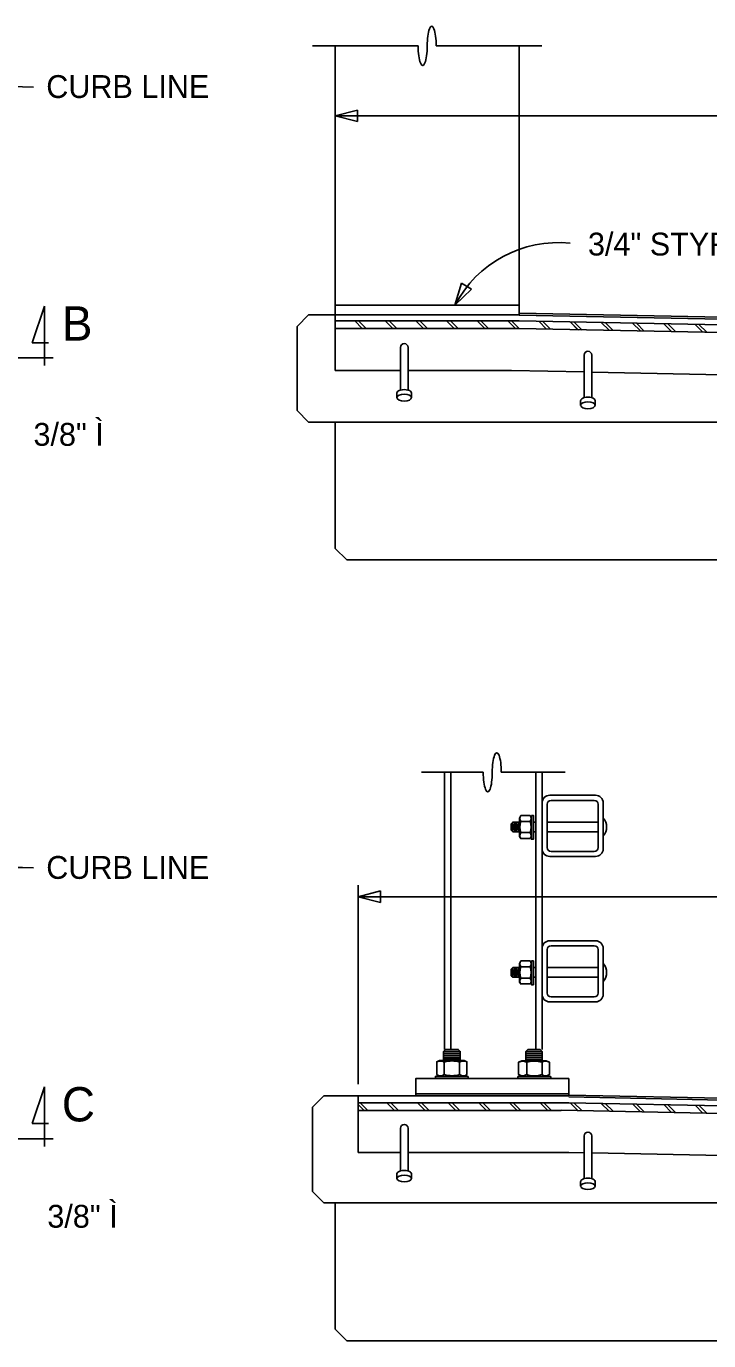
# Model space of a CAD drawing. Extents: x 19590 to 20151, y 19944 to 20103.
# Drawn here: x 19645.16 to 19659.09, y 20050.86 to 20077.69 of the extents above; entities that cross this region are included whole.
import ezdxf

# ---------------------------------------------------------------- set-up
doc = ezdxf.new("R2010")
doc.units = 0
doc.layers.add('DETAIL_PR', color=7, linetype='Continuous')
doc.layers.add('DETAIL_TEXT_DIMEN_PR', color=7, linetype='Continuous')

msp = doc.modelspace()

# ---------------------------------------------------------------- linework, layer by layer
at = {"layer": 'DETAIL_PR'}
for p, q in [((19650.997, 20077.285), (19653.156, 20077.285)), ((19651.466, 20071.795), (19651.466, 20077.285)), ((19653.525, 20077.285), (19655.684, 20077.285)), ((19655.216, 20071.795), (19655.216, 20077.285)), ((19651.466, 20071.995), (19655.216, 20071.995)), ((19650.919, 20071.795), (19650.684, 20071.56)), ((19650.919, 20071.795), (19651.466, 20071.795)), ((19651.466, 20070.66), (19651.466, 20071.795)), ((19651.466, 20071.795), (19655.216, 20071.795)), ((19651.466, 20071.673), (19655.216, 20071.673)), ((19652.017, 20071.517), (19651.861, 20071.673)), ((19652.095, 20071.517), (19651.939, 20071.673)), ((19652.642, 20071.517), (19652.486, 20071.673)), ((19652.72, 20071.517), (19652.564, 20071.673)), ((19653.267, 20071.517), (19653.111, 20071.673)), ((19653.345, 20071.517), (19653.189, 20071.673)), ((19653.892, 20071.517), (19653.736, 20071.673)), ((19653.97, 20071.517), (19653.814, 20071.673)), ((19654.517, 20071.517), (19654.361, 20071.673)), ((19654.595, 20071.517), (19654.439, 20071.673)), ((19655.142, 20071.517), (19654.986, 20071.673)), ((19655.22, 20071.517), (19655.064, 20071.673)), ((19671.778, 20071.498), (19655.216, 20071.829)), ((19671.778, 20071.459), (19655.216, 20071.79)), ((19671.778, 20071.342), (19655.216, 20071.673)), ((19650.684, 20069.842), (19650.684, 20071.56)), ((19651.466, 20071.517), (19655.216, 20071.517)), ((19671.622, 20071.188), (19655.216, 20071.517)), ((19655.779, 20071.505), (19655.619, 20071.665)), ((19655.858, 20071.504), (19655.699, 20071.663)), ((19656.416, 20071.493), (19656.257, 20071.652)), ((19656.427, 20071.482), (19656.257, 20071.652)), ((19656.496, 20071.491), (19656.337, 20071.65)), ((19656.505, 20071.482), (19656.337, 20071.65)), ((19657.054, 20071.48), (19656.895, 20071.638)), ((19657.052, 20071.482), (19656.895, 20071.638)), ((19657.134, 20071.478), (19656.974, 20071.638)), ((19657.134, 20071.478), (19656.974, 20071.638)), ((19657.692, 20071.467), (19657.532, 20071.627)), ((19657.692, 20071.467), (19657.532, 20071.627)), ((19657.772, 20071.465), (19657.612, 20071.625)), ((19657.772, 20071.465), (19657.612, 20071.625)), ((19658.33, 20071.454), (19658.17, 20071.614)), ((19658.409, 20071.453), (19658.25, 20071.612)), ((19658.967, 20071.442), (19658.808, 20071.601)), ((19659.047, 20071.44), (19658.888, 20071.599)), ((19652.794, 20071.13), (19652.794, 20070.262)), ((19652.95, 20071.13), (19652.95, 20070.262)), ((19656.544, 20070.974), (19656.544, 20070.106)), ((19656.7, 20070.974), (19656.7, 20070.106)), ((19651.466, 20070.66), (19652.794, 20070.66)), ((19652.95, 20070.66), (19654.2, 20070.66)), ((19654.2, 20070.66), (19655.059, 20070.66)), ((19656.544, 20070.63), (19655.059, 20070.66)), ((19660.293, 20070.555), (19656.7, 20070.627)), ((19652.723, 20070.201), (19652.723, 20070.105)), ((19653.02, 20070.201), (19653.02, 20070.105)), ((19650.919, 20069.607), (19650.684, 20069.842)), ((19656.473, 20070.045), (19656.473, 20069.949)), ((19656.77, 20070.045), (19656.77, 20069.949)), ((19650.919, 20069.607), (19670.763, 20069.607)), ((19651.466, 20067.029), (19651.466, 20069.607)), ((19651.466, 20067.029), (19651.7, 20066.795)), ((19651.7, 20066.795), (19674.434, 20066.795)), ((19653.225, 20062.459), (19654.484, 20062.459)), ((19653.693, 20062.459), (19653.693, 20056.803)), ((19653.822, 20062.459), (19653.822, 20056.803)), ((19654.853, 20062.459), (19656.154, 20062.459)), ((19655.557, 20062.459), (19655.557, 20056.8)), ((19655.686, 20062.459), (19655.686, 20056.8)), ((19655.686, 20060.896), (19655.686, 20061.834)), ((19655.789, 20060.923), (19655.789, 20061.807)), ((19656.779, 20061.99), (19655.842, 20061.99)), ((19656.752, 20061.885), (19655.868, 20061.885)), ((19656.83, 20060.923), (19656.83, 20061.807)), ((19656.934, 20060.896), (19656.934, 20061.834)), ((19655.086, 20061.442), (19655.086, 20061.245)), ((19655.113, 20061.402), (19655.113, 20061.282)), ((19655.127, 20061.442), (19655.127, 20061.245)), ((19655.141, 20061.402), (19655.141, 20061.282)), ((19655.154, 20061.442), (19655.154, 20061.245)), ((19655.175, 20061.402), (19655.175, 20061.282)), ((19655.195, 20061.442), (19655.195, 20061.245)), ((19655.208, 20061.402), (19655.208, 20061.282)), ((19655.441, 20061.456), (19655.249, 20061.456)), ((19655.441, 20061.228), (19655.249, 20061.228)), ((19655.509, 20061.442), (19655.536, 20061.442)), ((19655.509, 20061.244), (19655.536, 20061.244)), ((19655.789, 20061.441), (19656.83, 20061.441)), ((19655.789, 20061.244), (19656.83, 20061.244)), ((19656.779, 20060.741), (19655.842, 20060.741)), ((19656.752, 20060.845), (19655.868, 20060.845)), ((19655.686, 20057.927), (19655.686, 20058.865)), ((19655.789, 20057.954), (19655.789, 20058.838)), ((19656.779, 20059.021), (19655.842, 20059.021)), ((19656.752, 20058.917), (19655.868, 20058.917)), ((19656.83, 20057.954), (19656.83, 20058.838)), ((19656.934, 20057.927), (19656.934, 20058.865)), ((19655.086, 20058.473), (19655.086, 20058.276)), ((19655.113, 20058.434), (19655.113, 20058.313)), ((19655.127, 20058.473), (19655.127, 20058.276)), ((19655.141, 20058.434), (19655.141, 20058.313)), ((19655.154, 20058.473), (19655.154, 20058.276)), ((19655.175, 20058.434), (19655.175, 20058.313)), ((19655.195, 20058.473), (19655.195, 20058.276)), ((19655.208, 20058.434), (19655.208, 20058.313)), ((19655.441, 20058.488), (19655.249, 20058.488)), ((19655.441, 20058.26), (19655.249, 20058.26)), ((19655.509, 20058.473), (19655.536, 20058.473)), ((19655.509, 20058.275), (19655.536, 20058.275)), ((19655.789, 20058.472), (19656.83, 20058.472)), ((19655.789, 20058.275), (19656.83, 20058.275)), ((19656.779, 20057.772), (19655.842, 20057.772)), ((19656.752, 20057.876), (19655.868, 20057.876)), ((19654.015, 20056.762), (19653.674, 20056.762)), ((19654.015, 20056.722), (19653.674, 20056.722)), ((19654.015, 20056.681), (19653.674, 20056.681)), ((19655.685, 20056.76), (19655.357, 20056.76)), ((19655.685, 20056.72), (19655.357, 20056.72)), ((19655.685, 20056.679), (19655.357, 20056.679)), ((19654.015, 20056.641), (19653.674, 20056.641)), ((19654.015, 20056.601), (19653.674, 20056.601)), ((19653.688, 20056.547), (19653.688, 20056.292)), ((19654.001, 20056.547), (19654.001, 20056.292)), ((19655.685, 20056.639), (19655.357, 20056.639)), ((19655.685, 20056.599), (19655.357, 20056.599)), ((19655.372, 20056.545), (19655.372, 20056.289)), ((19655.685, 20056.545), (19655.685, 20056.289)), ((19651.231, 20055.857), (19650.997, 20055.623)), ((19651.231, 20055.857), (19656.231, 20055.857)), ((19651.934, 20054.699), (19651.934, 20055.857)), ((19671.987, 20055.556), (19656.231, 20055.871)), ((19650.997, 20053.904), (19650.997, 20055.623)), ((19651.934, 20055.715), (19656.231, 20055.715)), ((19652.052, 20055.559), (19651.934, 20055.676)), ((19652.13, 20055.559), (19651.974, 20055.715)), ((19652.677, 20055.559), (19652.52, 20055.715)), ((19652.755, 20055.559), (19652.599, 20055.715)), ((19653.302, 20055.559), (19653.145, 20055.715)), ((19653.38, 20055.559), (19653.224, 20055.715)), ((19653.927, 20055.559), (19653.77, 20055.715)), ((19654.005, 20055.559), (19653.849, 20055.715)), ((19654.552, 20055.559), (19654.395, 20055.715)), ((19654.63, 20055.559), (19654.474, 20055.715)), ((19655.177, 20055.559), (19655.02, 20055.715)), ((19655.255, 20055.559), (19655.099, 20055.715)), ((19655.802, 20055.559), (19655.645, 20055.715)), ((19655.88, 20055.559), (19655.724, 20055.715)), ((19671.778, 20055.521), (19656.231, 20055.832)), ((19671.778, 20055.404), (19656.231, 20055.715)), ((19656.416, 20055.555), (19656.257, 20055.715)), ((19656.496, 20055.553), (19656.337, 20055.713)), ((19657.052, 20055.545), (19656.895, 20055.701)), ((19657.134, 20055.541), (19656.974, 20055.7)), ((19657.692, 20055.53), (19657.532, 20055.689)), ((19657.772, 20055.528), (19657.612, 20055.687)), ((19658.33, 20055.517), (19658.17, 20055.676)), ((19658.409, 20055.515), (19658.25, 20055.675)), ((19658.967, 20055.504), (19658.808, 20055.664)), ((19659.047, 20055.502), (19658.888, 20055.662)), ((19651.934, 20055.559), (19656.075, 20055.559)), ((19671.622, 20055.251), (19656.075, 20055.562)), ((19652.794, 20055.193), (19652.794, 20054.324)), ((19652.95, 20055.193), (19652.95, 20054.324)), ((19656.544, 20055.037), (19656.544, 20054.168)), ((19656.7, 20055.037), (19656.7, 20054.168)), ((19651.934, 20054.699), (19652.794, 20054.699)), ((19652.95, 20054.699), (19654.669, 20054.699)), ((19654.669, 20054.699), (19656.231, 20054.699)), ((19656.544, 20054.693), (19656.231, 20054.699)), ((19660.293, 20054.618), (19656.7, 20054.69)), ((19652.723, 20054.264), (19652.723, 20054.168)), ((19653.02, 20054.264), (19653.02, 20054.168)), ((19656.473, 20054.108), (19656.473, 20054.012)), ((19656.77, 20054.108), (19656.77, 20054.012)), ((19651.231, 20053.67), (19650.997, 20053.904)), ((19651.231, 20053.67), (19670.763, 20053.67)), ((19651.466, 20051.092), (19651.466, 20053.67)), ((19651.466, 20051.092), (19651.7, 20050.857)), ((19651.7, 20050.857), (19674.434, 20050.857))]:
    msp.add_line(p, q, dxfattribs=at)
for points in [[(19655.249, 20061.578), (19655.222, 20061.524), (19655.222, 20061.147), (19655.249, 20061.107), (19655.441, 20061.107), (19655.468, 20061.147), (19655.468, 20061.524), (19655.441, 20061.578), (19655.249, 20061.578)], [(19655.468, 20061.578), (19655.468, 20061.093), (19655.509, 20061.093), (19655.509, 20061.578), (19655.468, 20061.578)], [(19655.222, 20061.442), (19655.086, 20061.442), (19655.058, 20061.41), (19655.058, 20061.275), (19655.086, 20061.245), (19655.222, 20061.245)], [(19655.249, 20058.61), (19655.222, 20058.556), (19655.222, 20058.178), (19655.249, 20058.138), (19655.441, 20058.138), (19655.468, 20058.178), (19655.468, 20058.556), (19655.441, 20058.61), (19655.249, 20058.61)], [(19655.468, 20058.61), (19655.468, 20058.124), (19655.509, 20058.124), (19655.509, 20058.61), (19655.468, 20058.61)], [(19655.222, 20058.473), (19655.086, 20058.473), (19655.058, 20058.442), (19655.058, 20058.306), (19655.086, 20058.276), (19655.222, 20058.276)], [(19654.015, 20056.574), (19654.015, 20056.762), (19653.974, 20056.802), (19653.714, 20056.802), (19653.674, 20056.762), (19653.674, 20056.574)], [(19655.685, 20056.572), (19655.685, 20056.76), (19655.644, 20056.8), (19655.398, 20056.8), (19655.357, 20056.76), (19655.357, 20056.572)], [(19653.592, 20056.251), (19654.097, 20056.251), (19654.152, 20056.292), (19654.152, 20056.547), (19654.097, 20056.574), (19653.592, 20056.574), (19653.538, 20056.547), (19653.538, 20056.292), (19653.592, 20056.251)], [(19655.275, 20056.249), (19655.767, 20056.249), (19655.835, 20056.289), (19655.835, 20056.545), (19655.767, 20056.572), (19655.275, 20056.572), (19655.207, 20056.545), (19655.207, 20056.289), (19655.275, 20056.249)], [(19654.179, 20056.251), (19653.51, 20056.251), (19653.51, 20056.211), (19654.179, 20056.211), (19654.179, 20056.251)], [(19655.862, 20056.249), (19655.194, 20056.249), (19655.194, 20056.209), (19655.862, 20056.209), (19655.862, 20056.249)]]:
    msp.add_lwpolyline(points, dxfattribs=at)
for points in [[(19656.231, 20055.896), (19653.106, 20055.896), (19653.106, 20056.209), (19656.231, 20056.209)], [(19653.106, 20055.896), (19656.231, 20055.896), (19656.231, 20055.857), (19653.106, 20055.857)]]:
    msp.add_lwpolyline(points, close=True, dxfattribs=at)
for centre, radius, start, end in [((19652.872, 20071.13), 0.0781, 0, 180), ((19656.622, 20070.974), 0.0781, 0, 180), ((19655.842, 20061.834), 0.156, 90, 180), ((19655.868, 20061.808), 0.0781, 90, 180), ((19656.752, 20061.808), 0.0781, 0, 90), ((19656.778, 20061.834), 0.156, 0, 90), ((19656.724, 20061.342), 0.279, 319.1029, 40.8971), ((19655.842, 20060.897), 0.156, 180, 270), ((19655.868, 20060.923), 0.0781, 180, 270), ((19656.752, 20060.923), 0.0781, 270, 360), ((19656.778, 20060.897), 0.156, 270, 360), ((19655.842, 20058.865), 0.156, 90, 180), ((19655.868, 20058.839), 0.0781, 90, 180), ((19656.752, 20058.839), 0.0781, 0, 90), ((19656.778, 20058.865), 0.156, 0, 90), ((19656.724, 20058.374), 0.279, 319.1029, 40.8971), ((19655.842, 20057.928), 0.156, 180, 270), ((19655.868, 20057.954), 0.0781, 180, 270), ((19656.752, 20057.954), 0.0781, 270, 360), ((19656.778, 20057.928), 0.156, 270, 360), ((19652.872, 20055.193), 0.0781, 0, 180), ((19656.622, 20055.037), 0.0781, 0, 180)]:
    msp.add_arc(centre, radius, start, end, dxfattribs=at)
for centre, major_axis, ratio, start_param, end_param in [((19653.433, 20077.285), (0, -0.4), 0.230204, 1.570796, 4.712389), ((19653.249, 20077.285), (0, -0.4), 0.230206, 4.712389, 7.853982), ((19652.872, 20070.202), (0.148, 0), 0.466726, 0, 3.141593), ((19656.622, 20070.046), (0.148, 0), 0.466726, 0, 3.141593), ((19654.761, 20062.459), (0, -0.4), 0.230204, 1.570796, 4.712389), ((19654.577, 20062.459), (0, -0.4), 0.230206, 4.712389, 7.853982), ((19655.341, 20061.519), (0.106, 0), 0.985841, 2.541474, 3.741711), ((19655.354, 20061.519), (0.106, 0), 0.985841, 5.683067, 6.883304), ((19655.632, 20061.341), (0.397, 0), 0.985841, 2.834625, 3.44856), ((19655.341, 20061.164), (0.106, 0), 0.985841, 2.541474, 3.741711), ((19655.063, 20061.341), (0.397, 0), 0.985841, 5.976218, 6.590153), ((19655.354, 20061.164), (0.106, 0), 0.985841, 5.683067, 6.883304), ((19655.341, 20058.55), (0.106, 0), 0.985841, 2.541474, 3.741711), ((19655.354, 20058.55), (0.106, 0), 0.985841, 5.683067, 6.883304), ((19655.632, 20058.372), (0.397, 0), 0.985841, 2.834625, 3.44856), ((19655.063, 20058.372), (0.397, 0), 0.985841, 5.976218, 6.590153), ((19655.341, 20058.195), (0.106, 0), 0.985841, 2.541474, 3.741711), ((19655.354, 20058.195), (0.106, 0), 0.985841, 5.683067, 6.883304), ((19653.612, 20056.43), (0.138, 0), 0.985841, 0.970676, 2.170917), ((19653.846, 20056.057), (0.517, 0), 0.985841, 1.263828, 1.877765), ((19654.08, 20056.43), (0.138, 0), 0.985841, 0.970677, 2.170916), ((19655.29, 20056.427), (0.138, 0), 0.985841, 0.970676, 2.170917), ((19655.524, 20056.054), (0.517, 0), 0.985841, 1.263828, 1.877765), ((19655.758, 20056.427), (0.138, 0), 0.985841, 0.970677, 2.170916), ((19653.612, 20056.403), (0.138, 0), 0.985841, 4.112273, 5.312505), ((19653.846, 20056.776), (0.517, 0), 0.985841, 4.405422, 5.019356), ((19654.08, 20056.403), (0.138, 0), 0.985841, 4.112272, 5.312505), ((19655.29, 20056.401), (0.138, 0), 0.985841, 4.112273, 5.312505), ((19655.524, 20056.774), (0.517, 0), 0.985841, 4.405422, 5.019356), ((19655.758, 20056.401), (0.138, 0), 0.985841, 4.112272, 5.312505), ((19652.872, 20054.265), (0.148, 0), 0.466726, 0, 3.141593), ((19656.622, 20054.108), (0.148, 0), 0.466726, 0, 3.141593)]:
    msp.add_ellipse(centre, major_axis=major_axis, ratio=ratio, start_param=start_param, end_param=end_param, dxfattribs=at)
for centre in [(19652.872, 20070.106), (19656.622, 20069.95), (19652.872, 20054.168), (19656.622, 20054.012)]:
    msp.add_ellipse(centre, major_axis=(0.148, 0), ratio=0.466726, dxfattribs=at)
at = {"layer": 'DETAIL_TEXT_DIMEN_PR'}
for p, q in [((19651.92, 20075.974), (19651.466, 20075.857)), ((19651.92, 20075.74), (19651.92, 20075.974)), ((19651.466, 20075.857), (19674.434, 20075.857)), ((19651.466, 20075.857), (19651.92, 20075.74)), ((19654.041, 20072.444), (19653.908, 20071.995)), ((19653.908, 20071.995), (19654.243, 20072.323)), ((19654.243, 20072.323), (19654.041, 20072.444)), ((19645.532, 20071.973), (19645.276, 20071.227)), ((19645.532, 20070.759), (19645.532, 20071.973)), ((19645.276, 20071.227), (19645.611, 20071.227)), ((19644.478, 20070.919), (19645.71, 20070.919)), ((19651.934, 20056.092), (19651.934, 20060.154)), ((19652.388, 20060.037), (19651.934, 20059.92)), ((19651.934, 20059.92), (19674.434, 20059.92)), ((19651.934, 20059.92), (19652.388, 20059.802)), ((19652.388, 20059.802), (19652.388, 20060.037)), ((19645.532, 20056.036), (19645.276, 20055.29)), ((19645.532, 20054.822), (19645.532, 20056.036)), ((19645.276, 20055.29), (19645.611, 20055.29)), ((19644.478, 20054.981), (19645.71, 20054.981))]:
    msp.add_line(p, q, dxfattribs=at)
for centre, radius, start, end in [((19644.125, 20036.781), 39.68, 88.2954, 93.5535), ((19656.016, 20070.892), 2.378, 84.1624, 152.3787), ((19644.125, 20020.844), 39.68, 88.2954, 93.5535)]:
    msp.add_arc(centre, radius, start, end, dxfattribs=at)

# ---------------------------------------------------------------- texts
for s, height, p in [('CURB LINE', 0.4665, (19645.566, 20076.222)), ('3/4" STYROFOAM', 0.46652, (19656.622, 20073.007)), ('B', 0.7, (19645.884, 20071.27)), ('3/8" Ì', 0.4665, (19645.305, 20069.123)), ('CURB LINE', 0.4665, (19645.566, 20060.284)), ('C', 0.7, (19645.884, 20055.333)), ('3/8" Ì', 0.4665, (19645.588, 20053.164))]:
    msp.add_text(s, height=height, dxfattribs=at).set_placement(p)

doc.saveas('drawing.dxf')
